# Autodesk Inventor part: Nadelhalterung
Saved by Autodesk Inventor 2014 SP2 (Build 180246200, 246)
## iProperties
Created: 2015-07
Part Number: Nadelhalterung
Material: Generisch
Document SubType Name: Modeling
Designer: e_krauts
Density: 1 g/cm^3
Appearance: Vorgabe
Author: e_krauts
Sending System: SolidWorks 2011
Last Author: e_boekem
Erstellt durch: XYZ
Werkstoff: AlCu4PbMg
Einheit: Stck.
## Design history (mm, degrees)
node "Nadelhalterung.ipt1"
node "Schnitt-Linear austragen2"
node "Basis1"
